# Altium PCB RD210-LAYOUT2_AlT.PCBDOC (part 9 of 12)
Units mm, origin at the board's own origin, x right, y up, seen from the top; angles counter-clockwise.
Board outline 250 x 123 mm, 4 copper layers (TOP, Mid-Layer 1, Mid-Layer 2, BOTTOM), stack 0.711 mm thick; 1043 components, 659 nets, 2786 pads, 1228 vias.
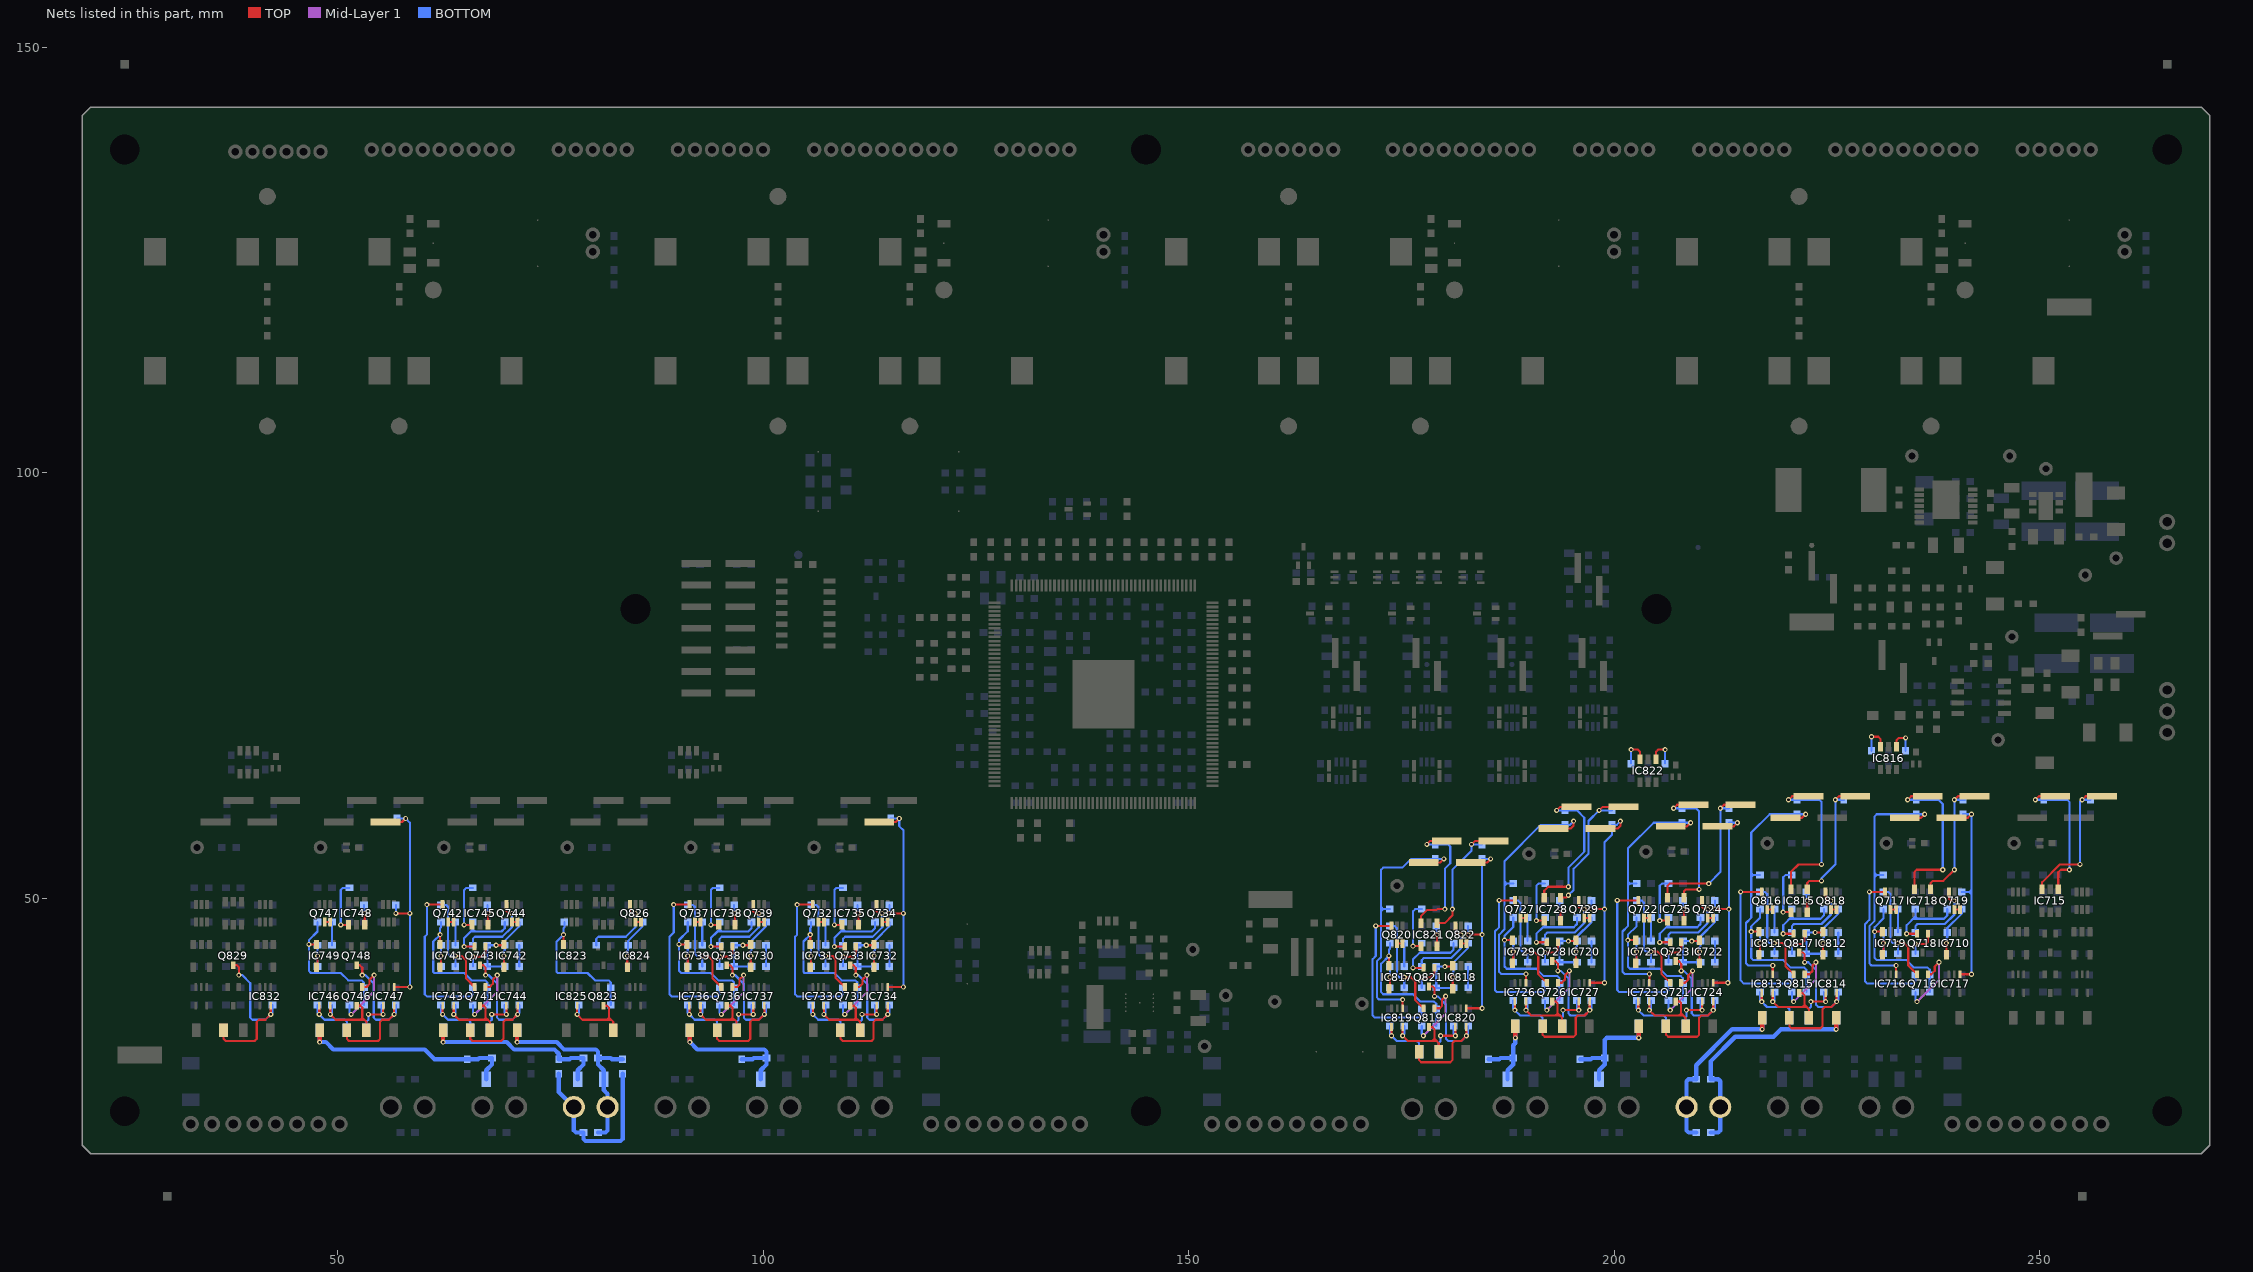
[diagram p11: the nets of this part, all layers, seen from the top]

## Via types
v1: diameter 0.6, hole 0.3, TOP to BOTTOM, 1134 vias
v2: diameter 1, hole 0.5, TOP to BOTTOM, 94 vias

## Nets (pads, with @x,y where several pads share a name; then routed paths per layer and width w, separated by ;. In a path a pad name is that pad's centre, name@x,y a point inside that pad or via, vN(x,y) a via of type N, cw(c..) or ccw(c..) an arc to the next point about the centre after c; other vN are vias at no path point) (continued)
N00300061: Q717.2 Q717.3 | length 0.6
  TOP w0.25: Q717.2@232.5,48.725 Q717.3@233.15,48.725
N00300062: C720.2 IC719.3 R822.1 R824.2 | length 16.8
  TOP w0.25: v1(230.625,46.1) IC719.3@231.55,46.1
  BOTTOM w0.25: C720.2@231.65,48.75 231.65,47.65 230.625,46.625 v1(230.625,46.1) 230.625,43 230.875,42.75 234.375,42.75 235.25,41.875 236.85,41.875 237.1,41.625 R822.1@237.1,41 R824.2@237.1,39
N00300063: Q717.6 R822.2 | length 19.4
  TOP w0.25: v1(230,50.775) Q717.6@231.85,50.775
  BOTTOM w0.25: v1(230,50.775) 230,47.5 229.5,47 229.5,40.25 229.75,40 235.15,40 235.4,40.25 R822.2@235.4,41
N00300064: Q716.1 R824.1 | length 9.1
  TOP w0.25: Q716.1@236.9,41.1 237.282,41.1 237.678,41.496 237.678,42.004 v1(238.186,42.512)
  Mid-Layer 1 w0.25: v1(235.6,37.875) 238.186,40.461 v1(238.186,42.512)
  BOTTOM w0.25: R824.1@235.4,39 235.4,38.075 v1(235.6,37.875)
N00300065: Q716.2 R826.1 R828.2 | length 13.7
  TOP w0.25: v1(233.35,44.75) 234.109,44.75 234.569,44.29 234.569,42.131 Q716.2@235.6,41.1
  BOTTOM w0.25: R828.2@231.65,50.75 232.25,50.75 232.5,50.5 232.5,45 232.75,44.75 v1(233.35,44.75) R826.1@233.35,43.5
N00300066: IC719.4 R820.1 R826.2 | length 3.9
  TOP w0.25: IC719.4@231.55,43.4 231.65,43.5 v1(231.65,44.75)
  BOTTOM w0.25: R826.2@231.65,43.5 v1(231.65,44.75) R820.1@231.65,46
N00300069: C720.1 R820.2 | length 2.8
  BOTTOM w0.25: R820.2@233.35,46 C720.1@233.35,48.75
N00300070: Q719.2 Q719.3 | length 0.7
  TOP w0.25: Q719.2@240,48.725 Q719.3@240.65,48.725
N00300071: Q719.6 R823.2 | length 9.1
  TOP w0.25: Q719.6@239.35,50.775 239.35,50 239.6,49.75 v1(240,49.75)
  BOTTOM w0.25: R823.2@235.4,46 235.4,46.75 235.65,47 238.875,47 240,48.125 v1(240,49.75)
N00300073: Q718.1 R825.1 | length 3.7
  TOP w0.25: v1(235.4,44.671) 236.662,44.671 236.9,44.909 Q718.1@236.9,45.85
  BOTTOM w0.25: R825.1@235.4,43.5 v1(235.4,44.671)
N00300074: Q718.2 R827.1 R829.2 | length 9.8
  TOP w0.25: v1(234.375,45.85) Q718.2@235.6,45.85
  BOTTOM w0.25: v1(234.375,45.85) 234.375,46.85 235.4,47.875 ; 235.15,47.625 235.65,47.625 ; R829.2@235.4,48.75 235.4,47.875 ; R827.1@239.15,48.75 239.15,48 238.775,47.625 235.65,47.625 ; 235.4,47.875 235.65,47.625
N00300075: IC710.4 R821.1 R827.2 | length 6.1
  TOP w0.25: IC710.4@239.05,43.4 v1(239.05,44.75)
  BOTTOM w0.25: v1(239.05,44.75) 239.05,45.3 239.15,45.4 R821.1@239.15,46 239.15,46.525 240.85,48.225 R827.2@240.85,48.75
N00300077: IC721.4 R740.1 R746.2 | length 3.9
  TOP w0.25: IC721.4@202.55,42.4 202.65,42.5 v1(202.65,43.75)
  BOTTOM w0.25: R746.2@202.65,42.5 v1(202.65,43.75) R740.1@202.65,45
N00300078: C730.1 R740.2 | length 2.7
  BOTTOM w0.25: R740.2@204.35,45 C730.1@204.35,47.75
N00300081: IC720.4 R841.1 R847.2 | length 6.1
  TOP w0.25: IC720.4@195.55,42.4 v1(195.55,43.75)
  BOTTOM w0.25: v1(195.55,43.75) 195.55,44.3 195.65,44.4 R841.1@195.65,45 195.65,45.525 197.35,47.225 R847.2@197.35,47.75
N00300082: C730.2 IC721.3 R742.1 R744.2 | length 16.8
  TOP w0.25: v1(201.625,45.1) IC721.3@202.55,45.1
  BOTTOM w0.25: C730.2@202.65,47.75 202.65,46.75 201.625,45.725 v1(201.625,45.1) 201.625,42 201.875,41.75 205.375,41.75 206.25,40.875 207.85,40.875 208.1,40.625 R742.1@208.1,40 R744.2@208.1,38
N00300083: Q723.1 R745.1 | length 3.7
  TOP w0.25: v1(206.4,43.655) 207.579,43.655 207.9,43.976 Q723.1@207.9,44.85
  BOTTOM w0.25: R745.1@206.4,42.5 v1(206.4,43.655)
N00300085: Q723.2 R747.1 R749.2 | length 9.8
  TOP w0.25: v1(205.375,44.85) Q723.2@206.6,44.85
  BOTTOM w0.25: v1(205.375,44.85) 205.375,45.85 206.15,46.625 ; R749.2@206.4,47.75 206.4,46.875 ; R747.1@210.15,47.75 210.15,47 209.775,46.625 206.65,46.625 ; 206.15,46.625 206.4,46.875 ; 206.15,46.625 206.65,46.625 ; 206.4,46.875 206.65,46.625
N00300087: Q728.2 R847.1 R849.2 | length 9.8
  TOP w0.25: v1(190.875,44.85) Q728.2@192.1,44.85
  BOTTOM w0.25: v1(190.875,44.85) 190.875,45.85 191.65,46.625 ; R849.2@191.9,47.75 191.9,46.875 ; R847.1@195.65,47.75 195.65,47 195.275,46.625 192.15,46.625 ; 191.65,46.625 191.9,46.875 ; 191.65,46.625 192.15,46.625 ; 191.9,46.875 192.15,46.625
N00300088: Q729.6 R843.2 | length 9.1
  TOP w0.25: Q729.6@195.85,49.775 195.85,49 196.1,48.75 v1(196.5,48.75)
  BOTTOM w0.25: R843.2@191.9,45 191.9,45.75 192.15,46 195.375,46 196.5,47.125 v1(196.5,48.75)
N00300090: C741.2 IC720.3 R843.1 R845.2 | length 6.5
  TOP w0.25: v1(194.625,45) 195.45,45 IC720.3@195.55,45.1
  BOTTOM w0.25: v1(194.625,45) R843.1@193.6,45 R845.2@193.6,42.5 C741.2@195.65,42.5
N00300093: C742.2 C743.2 R851.1 R853.2 R858.2 | length 11
  TOP w0.5: v1(188.4,33.625) R853.2@188.4,35
  BOTTOM w0.5: R858.2@185.25,31.1 186.5,31.1 186.65,31.25 C743.2@188.15,31.25 ; C742.2@187.475,28.75 187.475,29.825 188.15,30.5 C743.2@188.15,31.25 ; R851.1@188.4,35 v1(188.4,33.625) 188.4,33 188.15,32.75 C743.2@188.15,31.25
N00300094: C740.2 IC729.3 R842.1 R844.2 | length 16.8
  TOP w0.25: v1(187.125,45.1) IC729.3@188.05,45.1
  BOTTOM w0.25: C740.2@188.15,47.75 188.15,46.65 187.125,45.625 v1(187.125,45.1) 187.125,42 187.375,41.75 190.875,41.75 191.75,40.875 193.35,40.875 193.6,40.625 R842.1@193.6,40 R844.2@193.6,38
N00300095: Q729.2 Q729.3 | length 0.6
  TOP w0.25: Q729.2@196.5,47.725 Q729.3@197.15,47.725
N00300096: C740.1 R840.2 | length 2.7
  BOTTOM w0.25: R840.2@189.85,45 C740.1@189.85,47.75
N00300097: IC729.4 R840.1 R846.2 | length 3.9
  TOP w0.25: IC729.4@188.05,42.4 188.15,42.5 v1(188.15,43.75)
  BOTTOM w0.25: R846.2@188.15,42.5 v1(188.15,43.75) R840.1@188.15,45
N00300098: Q726.2 R846.1 R848.2 | length 13.7
  TOP w0.25: v1(189.85,43.75) 190.609,43.75 191.085,43.274 191.085,41.115 Q726.2@192.1,40.1
  BOTTOM w0.25: R848.2@188.15,49.75 188.75,49.75 189,49.5 189,44 189.25,43.75 v1(189.85,43.75) R846.1@189.85,42.5
N00300099: C734.2 IC723.4 R751.2 | length 6.8
  TOP w0.25: v1(202.85,36.875) IC723.4@202.85,37.9
  BOTTOM w0.25: C734.2@202.65,38 202.65,37.075 v1(202.85,36.875) 203.475,36.25 205.85,36.25 206.1,36 R751.2@206.1,35
N00300100: C735.1 IC724.5 Q723.3 R753.1 | length 21.5
  TOP w0.25: R753.1@206.1,35 206.1,34 206.35,33.75 209.75,33.75 210,34 210,36 210.25,36.25 211.025,36.25 v1(211.65,36.875) IC724.5@211.65,37.9 ; Q723.3@207.25,42.65 207.568,42.65 207.9,42.318 v1(207.9,41.5)
  BOTTOM w0.25: v1(207.9,41.5) 208.21,41.5 209.125,40.585 209.125,36.5 209.375,36.25 211.025,36.25 v1(211.65,36.875) 211.85,37.075 C735.1@211.85,38
N00300103: C745.1 IC727.5 Q728.3 R853.1 | length 21.6
  TOP w0.25: R853.1@191.6,35 191.6,34 191.85,33.75 195.25,33.75 195.5,34 195.5,36 195.75,36.25 196.525,36.25 v1(197.15,36.875) IC727.5@197.15,37.9 ; Q728.3@192.75,42.65 193.101,42.65 193.4,42.351 v1(193.4,41.5)
  BOTTOM w0.25: v1(193.4,41.5) 193.732,41.5 194.625,40.607 194.625,36.5 194.875,36.25 196.525,36.25 v1(197.15,36.875) 197.35,37.075 C745.1@197.35,38
N00300105: Q722.6 R742.2 | length 20
  TOP w0.25: v1(200.375,49.775) Q722.6@202.85,49.775
  BOTTOM w0.25: v1(200.375,49.775) 200.375,39.25 200.625,39 206.15,39 206.4,39.25 R742.2@206.4,40
N00300107: C731.1 R741.2 | length 2.5
  BOTTOM w0.25: C731.1@211.85,42.5 R741.2@211.85,45
N00300108: Q721.2 R746.1 R748.2 | length 13.7
  TOP w0.25: v1(204.35,43.75) 205.109,43.75 205.585,43.274 205.585,41.115 Q721.2@206.6,40.1
  BOTTOM w0.25: R748.2@202.65,49.75 203.25,49.75 203.5,49.5 203.5,44 203.75,43.75 v1(204.35,43.75) R746.1@204.35,42.5
N00300111: C744.2 IC726.4 R851.2 | length 6.8
  TOP w0.25: v1(188.35,36.875) IC726.4@188.35,37.9
  BOTTOM w0.25: C744.2@188.15,38 188.15,37.075 v1(188.35,36.875) 188.975,36.25 191.35,36.25 191.6,36 R851.2@191.6,35
N00300112: Q727.6 R842.2 | length 19.4
  TOP w0.25: v1(186.5,49.775) Q727.6@188.35,49.775
  BOTTOM w0.25: v1(186.5,49.775) 186.5,46.625 186,46.125 186,39.25 186.25,39 191.65,39 191.9,39.25 R842.2@191.9,40
N00300113: C744.1 IC726.5 Q726.3 R850.2 | length 10.5
  TOP w0.25: IC726.5@189.65,37.9 v1(189.65,36.875) 190.275,36.25 193.125,36.25 ; Q726.3@192.75,37.9 193.141,37.9 193.375,37.666 193.375,36.525 ; R850.2@193.9,35 193.9,36 193.65,36.25 ; 193.125,36.25 193.375,36.5 193.375,36.525 ; 193.125,36.25 193.65,36.25 ; 193.375,36.525 193.65,36.25
  BOTTOM w0.25: v1(189.65,36.875) 189.85,37.075 C744.1@189.85,38
N00300115: C735.2 IC724.4 R752.2 | length 6
  TOP w0.25: v1(208.5,36.875) v1(210.35,36.875) IC724.4@210.35,37.9
  BOTTOM w0.25: R752.2@208.4,35 208.4,36.025 208.5,36.125 v1(208.5,36.875) ; C735.2@210.15,38 210.15,37.075 v1(210.35,36.875)
N00300117: Q728.1 R845.1 | length 3.7
  TOP w0.25: v1(191.9,43.655) 193.101,43.655 193.4,43.954 Q728.1@193.4,44.85
  BOTTOM w0.25: R845.1@191.9,42.5 v1(191.9,43.655)
N00300122: C731.2 IC722.3 R743.1 R745.2 | length 6.5
  TOP w0.25: v1(209.125,45) 209.95,45 IC722.3@210.05,45.1
  BOTTOM w0.25: v1(209.125,45) R743.1@208.1,45 R745.2@208.1,42.5 C731.2@210.15,42.5
N00300123: IC722.4 R741.1 R747.2 | length 6.1
  TOP w0.25: IC722.4@210.05,42.4 v1(210.05,43.75)
  BOTTOM w0.25: v1(210.05,43.75) 210.05,44.3 210.15,44.4 R741.1@210.15,45 210.15,45.525 211.85,47.225 R747.2@211.85,47.75
N00300124: C741.1 R841.2 | length 2.5
  BOTTOM w0.25: C741.1@197.35,42.5 R841.2@197.35,45
N00300126: Q727.2 Q727.3 | length 0.7
  TOP w0.25: Q727.2@189,47.725 Q727.3@189.65,47.725
N00300131: C734.1 IC723.5 Q721.3 R750.2 | length 10.5
  TOP w0.25: IC723.5@204.15,37.9 v1(204.15,36.875) 204.775,36.25 207.625,36.25 ; Q721.3@207.25,37.9 207.706,37.9 207.875,37.731 207.875,36.525 207.888,36.512 ; R750.2@208.4,35 208.4,36 208.15,36.25 ; 207.625,36.25 207.888,36.512 ; 207.625,36.25 208.15,36.25 ; 207.888,36.512 208.15,36.25
  BOTTOM w0.25: v1(204.15,36.875) 204.35,37.075 C734.1@204.35,38
N00300133: IC725.6 R756.1 | length 2.4
  TOP w0.25: IC725.6@208.2,47.4 v1(208.2,48.75)
  BOTTOM w0.25: R756.1@208.1,49.75 208.1,49.225 208.2,49.125 v1(208.2,48.75)
N00300134: C732.2 C733.2 R751.1 R753.2 R758.2 | length 14.7
  TOP w0.5: v1(202.9,33.625) R753.2@202.9,35
  BOTTOM w0.5: R758.2@196,31.1 197.25,31.1 197.4,31.25 C733.2@198.9,31.25 ; C732.2@198.225,28.75 198.225,29.825 198.9,30.5 C733.2@198.9,31.25 ; R751.1@202.9,35 v1(202.9,33.625) 199.15,33.625 198.9,33.375 C733.2@198.9,31.25
N00300135: IC725.4 R757.1 | length 6.2
  TOP w0.25: v1(205.375,47.4) IC725.4@206.3,47.4
  BOTTOM w0.25: v1(205.375,47.4) 205.375,51.5 205.625,51.75 R757.1@206.4,51.75
N00300136: Q722.2 Q722.3 | length 0.7
  TOP w0.25: Q722.2@203.5,47.725 Q722.3@204.15,47.725
N00300138: Q721.1 R744.1 | length 9.1
  TOP w0.25: Q721.1@207.9,40.1 208.342,40.1 208.722,40.48 208.722,40.988 v1(209.23,41.496)
  Mid-Layer 1 w0.25: v1(206.6,36.875) 209.23,39.505 v1(209.23,41.496)
  BOTTOM w0.25: R744.1@206.4,38 206.4,37.075 v1(206.6,36.875)
N00300139: Q724.2 Q724.3 | length 0.7
  TOP w0.25: Q724.2@211,47.725 Q724.3@211.65,47.725
N00300141: Q724.6 R743.2 | length 9.1
  TOP w0.25: Q724.6@210.35,49.775 210.35,49 210.6,48.75 v1(211,48.75)
  BOTTOM w0.25: R743.2@206.4,45 206.4,45.75 206.65,46 209.875,46 211,47.125 v1(211,48.75)
N00300142: C745.2 IC727.4 R852.2 | length 6
  TOP w0.25: v1(194,36.875) v1(195.85,36.875) IC727.4@195.85,37.9
  BOTTOM w0.25: R852.2@193.9,35 193.9,36.025 194,36.125 v1(194,36.875) ; C745.2@195.65,38 195.65,37.075 v1(195.85,36.875)
N00300148: IC728.6 R856.1 | length 2.4
  TOP w0.25: IC728.6@193.7,47.4 v1(193.7,48.75)
  BOTTOM w0.25: R856.1@193.6,49.75 193.6,49.225 193.7,49.125 v1(193.7,48.75)
N00300149: IC728.4 R857.1 | length 6.2
  TOP w0.25: v1(190.875,47.4) IC728.4@191.8,47.4
  BOTTOM w0.25: v1(190.875,47.4) 190.875,51.5 191.125,51.75 R857.1@191.9,51.75
N00300150: Q726.1 R844.1 | length 9.2
  TOP w0.25: Q726.1@193.4,40.1 193.863,40.1 194.244,40.481 194.244,40.988 v1(194.752,41.496)
  Mid-Layer 1 w0.25: v1(192.1,36.875) 194.752,39.527 v1(194.752,41.496)
  BOTTOM w0.25: R844.1@191.9,38 191.9,37.075 v1(192.1,36.875)
N00300153: CN501.2 IC715.1 R701.2 | length 18
  TOP w0.25: v1(249.5,61.6) 249.92,62.02 CN501.2@251.85,62.02 ; IC715.1@252.2,51.1 252.2,53.075 252.5,53.375 v1(253.5,53.375)
  BOTTOM w0.25: v1(249.5,61.6) R701.2@250.5,61.6 253.25,61.6 253.5,61.35 v1(253.5,53.375)
N00300157: IC816.6 R706.1 | length 3.7
  TOP w0.25: v1(230.25,69) 231.05,69 231.3,68.75 IC816.6@231.3,67.85
  BOTTOM w0.25: R706.1@230.25,67.35 v1(230.25,69)
N00300158: IC816.4 R906.1 | length 3.5
  TOP w0.25: IC816.4@233.2,67.85 233.2,68.625 233.45,68.875 v1(234.25,68.875)
  BOTTOM w0.25: R906.1@234.25,67.35 v1(234.25,68.875)
N00300160: CN503.2 IC715.3 R901.2 | length 17.4
  TOP w0.25: IC715.3@250.3,51.1 250.3,51.925 252.375,54 v1(254.75,54) ; v1(255,61.6) 255.42,62.02 CN503.2@257.35,62.02
  BOTTOM w0.25: v1(254.75,54) 254.75,61.35 v1(255,61.6) R901.2@256,61.6
N00300161: CN921.1 IC819.1 R717.1 R954.1 | length 31.3
  TOP w0.25: IC819.1@175.15,37.1 v1(175.15,38.125) ; CN921.1@177.65,54.23 179.58,54.23 v1(180,54.65)
  BOTTOM w0.25: R954.1@173.65,48.75 172.875,48.75 ; v1(175.15,38.125) 172.375,38.125 172.125,38.375 172.125,42.625 172.625,43.125 172.625,48.5 ; v1(180,54.65) R717.1@179,54.65 176.15,54.65 175.125,53.625 172.875,53.625 172.625,53.375 172.625,49 ; 172.625,48.5 172.625,49 ; 172.625,48.5 172.875,48.75 ; 172.625,49 172.875,48.75
N00300164: CN913.2 IC815.1 R916.2 | length 16.2
  TOP w0.25: IC815.1@222.7,51.1 222.7,51.825 222.95,52.075 v1(224.375,52.075) ; v1(226,61.6) 226.42,62.02 CN913.2@228.35,62.02
  BOTTOM w0.25: v1(224.375,52.075) 224.375,52.375 226,54 v1(226,61.6) R916.2@227,61.6
N00300165: CN911.1 IC813.1 R716.1 R934.1 | length 31.2
  TOP w0.25: IC813.1@218.65,41.1 v1(218.65,42.125) ; CN911.1@220.15,59.48 222.08,59.48 v1(222.5,59.9)
  BOTTOM w0.25: R934.1@217.15,52.75 216.375,52.75 ; v1(218.65,42.125) 215.75,42.125 215.5,42.375 215.5,47.125 216.125,47.75 216.125,52.5 ; v1(222.5,59.9) R716.1@221.5,59.9 218.275,59.9 216.125,57.75 216.125,53 ; 216.125,52.5 216.375,52.75 ; 216.125,52.5 216.125,53 ; 216.125,53 216.375,52.75
N00300168: C924.1 IC819.5 Q819.3 R950.2 | length 10.4
  TOP w0.25: IC819.5@175.15,34.9 v1(175.15,33.875) 175.775,33.25 178.65,33.25 ; Q819.3@178.25,34.9 178.638,34.9 178.9,34.638 178.9,33.5 ; R950.2@179.4,32 179.4,33 179.15,33.25 ; 178.65,33.25 179.15,33.25 ; 178.65,33.25 178.9,33.5 ; 178.9,33.5 179.15,33.25
  BOTTOM w0.25: v1(175.15,33.875) 175.35,34.075 C924.1@175.35,35
N00300169: CN923.1 IC820.1 R917.1 R955.1 | length 25.6
  TOP w0.25: IC820.1@182.65,37.1 v1(184.5,37.1) ; v1(182.85,45.75) v1(184.5,45.75) ; CN923.1@183.15,54.23 185.08,54.23 v1(185.5,54.65)
  BOTTOM w0.25: v1(182.85,45.75) R955.1@182.85,46.75 ; v1(184.5,37.1) v1(184.5,45.75) R917.1@184.5,54.65 v1(185.5,54.65)
N00300170: CN923.2 IC821.1 R917.2 | length 15.5
  TOP w0.25: IC821.1@179.2,47.1 180.1,47.1 181,48 v1(181,48.75) ; v1(183.25,56.35) 183.67,56.77 CN923.2@185.85,56.77
  BOTTOM w0.25: v1(181,48.75) 181,53.375 183.25,55.625 v1(183.25,56.35) R917.2@184.5,56.35
N00300171: CN504.1 IC716.1 R711.1 R834.1 | length 31.8
  TOP w0.25: IC716.1@233.15,41.1 v1(233.15,42.125) ; CN504.1@234.15,59.48 236.08,59.48 v1(236.5,59.9)
  BOTTOM w0.25: R834.1@231.65,52.75 230.875,52.75 ; v1(233.15,42.125) 230.25,42.125 230,42.375 230,46.75 230.625,47.375 230.625,52.5 ; v1(236.5,59.9) R711.1@235.5,59.9 230.875,59.9 230.625,59.65 230.625,53 ; 230.625,52.5 230.875,52.75 ; 230.625,52.5 230.625,53 ; 230.625,53 230.875,52.75
N00300173: CN506.1 IC717.1 R835.1 R911.1 | length 25.3
  TOP w0.25: CN506.1@239.65,59.48 241.58,59.48 v1(242,59.9) ; IC717.1@240.65,41.1 v1(242,41.1)
  BOTTOM w0.25: R835.1@240.85,50.75 241.75,50.75 ; R911.1@241,59.9 v1(242,59.9) 242,51 ; v1(242,41.1) 242,50.5 ; 241.75,50.75 242,51 ; 241.75,50.75 242,50.5 ; 242,50.5 242,51
N00300179: C924.2 IC819.4 R951.2 | length 6.8
  TOP w0.25: v1(173.85,33.875) IC819.4@173.85,34.9
  BOTTOM w0.25: C924.2@173.65,35 173.65,34.075 v1(173.85,33.875) 174.475,33.25 176.85,33.25 177.1,33 R951.2@177.1,32
N00300180: C925.2 IC820.4 R952.2 | length 5.9
  TOP w0.25: v1(179.625,33.875) v1(181.35,33.875) IC820.4@181.35,34.9
  BOTTOM w0.25: R952.2@179.4,32 179.4,33.025 179.625,33.25 v1(179.625,33.875) ; C925.2@181.15,35 181.15,34.075 v1(181.35,33.875)
N00300183: C925.1 IC820.5 Q821.3 R953.1 | length 21.6
  TOP w0.25: R953.1@177.1,32 177.1,31 177.35,30.75 180.75,30.75 181,31 181,33 181.25,33.25 182.025,33.25 v1(182.65,33.875) IC820.5@182.65,34.9 ; Q821.3@178.25,39.65 178.714,39.65 178.9,39.464 v1(178.9,38.5)
  BOTTOM w0.25: v1(178.9,38.5) 179.27,38.5 180.25,37.519 180.25,33.5 180.5,33.25 182.025,33.25 v1(182.65,33.875) 182.85,34.075 C925.1@182.85,35
N00300185: IC821.4 R957.1 | length 6.2
  TOP w0.25: v1(176.375,44.4) IC821.4@177.3,44.4
  BOTTOM w0.25: v1(176.375,44.4) 176.375,48.5 176.625,48.75 R957.1@177.4,48.75
N00300186: IC821.6 R956.1 | length 2.4
  TOP w0.25: IC821.6@179.2,44.4 v1(179.2,45.75)
  BOTTOM w0.25: R956.1@179.1,46.75 179.1,46.225 179.2,46.125 v1(179.2,45.75)
N00300187: Q820.6 R942.2 | length 19.3
  TOP w0.25: v1(172,46.775) Q820.6@173.85,46.775
  BOTTOM w0.25: v1(172,46.775) 172,43.25 171.625,42.875 171.625,36.25 171.875,36 177.15,36 177.4,36.25 R942.2@177.4,37
N00300188: Q820.2 Q820.3 | length 0.7
  TOP w0.25: Q820.2@174.5,44.725 Q820.3@175.15,44.725
N00300189: Q819.1 R944.1 | length 9.2
  TOP w0.25: Q819.1@178.9,37.1 179.512,37.1 179.766,37.354 179.766,38.067 v1(180.211,38.511)
  Mid-Layer 1 w0.25: v1(177.6,33.875) 180.211,36.486 v1(180.211,38.511)
  BOTTOM w0.25: R944.1@177.4,35 177.4,34.075 v1(177.6,33.875)
N00300190: Q819.2 R946.1 R948.2 | length 13.7
  TOP w0.25: v1(175.35,40.75) 176.116,40.75 176.64,40.226 176.64,38.06 Q819.2@177.6,37.1
  BOTTOM w0.25: R948.2@173.65,46.75 174.25,46.75 174.5,46.5 174.5,41 174.75,40.75 v1(175.35,40.75) R946.1@175.35,39.5
N00300191: CN911.2 IC815.3 R716.2 | length 19.8
  TOP w0.25: v1(220.5,61.6) 220.92,62.02 CN911.2@222.85,62.02 ; IC815.3@220.8,51.1 220.8,53.125 221.675,54 v1(224.375,54)
  BOTTOM w0.25: v1(220.5,61.6) R716.2@221.5,61.6 224.125,61.6 224.375,61.35 v1(224.375,54)
N00300193: C920.2 IC817.3 R942.1 R944.2 | length 17
  TOP w0.25: IC817.3@173.55,42.1 v1(173.55,43.25)
  BOTTOM w0.25: C920.2@173.65,44.75 173.65,44.1 173.55,44 v1(173.55,43.25) 172.625,42.325 172.625,39 172.875,38.75 176.375,38.75 177.25,37.875 178.85,37.875 179.1,37.625 R942.1@179.1,37 R944.2@179.1,35
N00300194: IC817.4 R940.1 R946.2 | length 3.9
  TOP w0.25: IC817.4@173.55,39.4 173.65,39.5 v1(173.65,40.75)
  BOTTOM w0.25: R946.2@173.65,39.5 v1(173.65,40.75) R940.1@173.65,42
N00300195: C920.1 R940.2 | length 2.7
  BOTTOM w0.25: R940.2@175.35,42 C920.1@175.35,44.75
N00300198: Q822.2 Q822.3 | length 0.6
  TOP w0.25: Q822.2@182,44.725 Q822.3@182.65,44.725
N00300199: C921.2 IC818.3 R943.1 R945.2 | length 6.5
  TOP w0.25: v1(180.125,42) 180.95,42 IC818.3@181.05,42.1
  BOTTOM w0.25: v1(180.125,42) R943.1@179.1,42 R945.2@179.1,39.5 C921.2@181.15,39.5
N00300200: Q822.6 R943.2 | length 9.1
  TOP w0.25: Q822.6@181.35,46.775 181.35,46 181.6,45.75 v1(182,45.75)
  BOTTOM w0.25: R943.2@177.4,42 177.4,42.75 177.65,43 180.875,43 182,44.125 v1(182,45.75)
N00300201: Q821.1 R945.1 | length 3.6
  TOP w0.25: v1(177.4,40.734) 178.496,40.734 178.9,41.138 Q821.1@178.9,41.85
  BOTTOM w0.25: R945.1@177.4,39.5 v1(177.4,40.734)
N00300202: Q821.2 R947.1 R949.2 | length 9.8
  TOP w0.25: v1(176.375,41.85) Q821.2@177.6,41.85
  BOTTOM w0.25: v1(176.375,41.85) 176.375,42.85 177.15,43.625 ; R949.2@177.4,44.75 177.4,43.875 ; R947.1@181.15,44.75 181.15,44 180.775,43.625 177.65,43.625 ; 177.15,43.625 177.4,43.875 ; 177.15,43.625 177.65,43.625 ; 177.4,43.875 177.65,43.625
N00300203: IC818.4 R941.1 R947.2 | length 6.1
  TOP w0.25: IC818.4@181.05,39.4 v1(181.05,40.75)
  BOTTOM w0.25: v1(181.05,40.75) 181.05,41.3 181.15,41.4 R941.1@181.15,42 181.15,42.525 182.85,44.225 R947.2@182.85,44.75
N00300207: C921.1 R941.2 | length 2.5
  BOTTOM w0.25: C921.1@182.85,39.5 R941.2@182.85,42
N00300210: IC822.6 R707.1 | length 3.7
  TOP w0.25: v1(202,67.5) 202.8,67.5 203.05,67.25 IC822.6@203.05,66.35
  BOTTOM w0.25: R707.1@202,65.85 v1(202,67.5)
N00300213: IC822.4 R907.1 | length 3.7
  TOP w0.25: IC822.4@204.95,66.35 204.95,67.25 205.2,67.5 v1(206,67.5)
  BOTTOM w0.25: R907.1@206,65.85 v1(206,67.5)
N00300216: CN513.2 IC725.3 R902.2 | length 19.3
  TOP w0.25: IC725.3@206.3,50.1 206.3,51.5 206.55,51.75 v1(211.125,51.75) ; v1(212.5,60.6) 212.92,61.02 CN513.2@214.85,61.02
  BOTTOM w0.25: v1(211.125,51.75) 212.5,53.125 v1(212.5,60.6) R902.2@213.5,60.6
N00300217: CN516.2 IC728.1 R912.2 | length 17
  TOP w0.25: IC728.1@193.7,50.1 194.35,50.1 v1(194.625,50.375) ; v1(198.25,60.35) 198.67,60.77 CN516.2@201.1,60.77
  BOTTOM w0.25: v1(194.625,50.375) 195.25,51 195.25,53.5 197,55.25 197,59.1 v1(198.25,60.35) R912.2@199.75,60.35
N00300218: CN506.2 IC718.1 R911.2 | length 16.4
  TOP w0.25: IC718.1@237.2,51.1 237.2,51.825 237.45,52.075 238.7,52.075 v1(240,53.375) ; v1(240,61.6) 240.42,62.02 CN506.2@242.35,62.02 CN506.2@242.6,62.02
  BOTTOM w0.25: v1(240,53.375) v1(240,61.6) R911.2@241,61.6 R911.2@241.25,61.6
N00300219: CN513.1 IC724.1 R755.1 R902.1 | length 26.8
  TOP w0.25: IC724.1@211.65,40.1 v1(213.375,40.1) ; v1(211.85,48.75) v1(213.5,48.75) ; CN513.1@212.15,58.48 214.08,58.48 v1(214.5,58.9)
  BOTTOM w0.25: v1(211.85,48.75) R755.1@211.85,49.75 ; v1(213.375,40.1) 213.5,40.225 v1(213.5,48.75) R902.1@213.5,58.9 v1(214.5,58.9)
N00300220: CN514.2 IC728.3 R712.2 | length 18.9
  TOP w0.25: IC728.3@191.8,50.1 191.8,50.925 192.25,51.375 v1(194.625,51.375) ; v1(193.25,60.35) 193.67,60.77 CN514.2@195.6,60.77
  BOTTOM w0.25: v1(193.25,60.35) R712.2@194.25,60.35 195.65,60.35 196.5,59.5 196.5,55.5 194.625,53.625 v1(194.625,51.375)
N00300221: CN511.1 IC723.1 R702.1 R754.1 | length 31.7
  TOP w0.25: IC723.1@204.15,40.1 v1(204.15,41.125) ; CN511.1@206.65,58.48 208.58,58.48 v1(209,58.9)
  BOTTOM w0.25: R754.1@202.65,51.75 201.875,51.75 ; v1(204.15,41.125) 201.25,41.125 201,41.375 201,46.125 201.625,46.75 201.625,51.5 ; v1(209,58.9) R702.1@208,58.9 204.65,58.9 201.625,55.875 201.625,52 ; 201.625,51.5 201.875,51.75 ; 201.625,51.5 201.625,52 ; 201.625,52 201.875,51.75
N00300222: CN516.1 IC727.1 R855.1 R912.1 | length 27.4
  TOP w0.25: IC727.1@197.15,40.1 v1(198.875,40.1) ; v1(197.35,48.75) v1(198.875,48.75) ; CN516.1@198.4,58.23 200.437,58.23 200.75,58.543 v1(200.75,59.085)
  BOTTOM w0.25: v1(197.35,48.75) R855.1@197.35,49.75 ; v1(198.875,40.1) v1(198.875,48.75) 198.875,56.625 199.75,57.5 R912.1@199.75,58.65 200.314,58.65 v1(200.75,59.085)
N00300223: CN504.2 IC718.3 R711.2 | length 20.3
  TOP w0.25: v1(234.5,61.6) 234.92,62.02 CN504.2@236.85,62.02 CN504.2@237.1,62.02 ; IC718.3@235.3,51.1 235.3,53.125 235.55,53.375 v1(238.625,53.375)
  BOTTOM w0.25: v1(234.5,61.6) R711.2@235.5,61.6 238.125,61.6 238.625,61.1 v1(238.625,53.375)
N00300224: CN511.2 IC725.1 R702.2 | length 17.5
  TOP w0.25: v1(207,60.6) 207.42,61.02 CN511.2@209.35,61.02 ; IC725.1@208.2,50.1 208.2,50.825 208.45,51.075 v1(210,51.075)
  BOTTOM w0.25: v1(207,60.6) R702.2@208,60.6 209.625,60.6 210,60.225 v1(210,51.075)
N00300225: CN921.2 IC821.3 R717.2 | length 17
  TOP w0.25: IC821.3@177.3,47.1 177.3,47.925 178,48.625 179.125,48.625 179.25,48.75 v1(180.125,48.75) ; v1(178,56.35) 178.42,56.77 CN921.2@180.35,56.77
  BOTTOM w0.25: v1(178,56.35) R717.2@179,56.35 180.5,56.35 180.75,56.1 180.75,54.125 180.125,53.5 v1(180.125,48.75)
N00300228: CN514.1 IC726.1 R712.1 R854.1 | length 32.1
  TOP w0.25: IC726.1@189.65,40.1 v1(189.65,41.125) ; CN514.1@192.9,58.23 194.913,58.23 195.25,58.567 v1(195.25,59.085)
  BOTTOM w0.25: R854.1@188.15,51.75 187.375,51.75 ; v1(189.65,41.125) 186.75,41.125 186.5,41.375 186.5,45.75 187.125,46.375 187.125,51.5 ; v1(195.25,59.085) 194.805,58.641 194.241,58.641 R712.1@194.25,58.65 191.4,58.65 187.125,54.375 187.125,52 ; 187.125,51.5 187.375,51.75 ; 187.125,51.5 187.125,52 ; 187.125,52 187.375,51.75
N00300229: IC811.4 R920.1 R926.2 | length 3.9
  TOP w0.25: IC811.4@217.05,43.4 217.15,43.5 v1(217.15,44.75)
  BOTTOM w0.25: R926.2@217.15,43.5 v1(217.15,44.75) R920.1@217.15,46
N00300230: C910.1 R920.2 | length 2.8
  BOTTOM w0.25: R920.2@218.85,46 C910.1@218.85,48.75
N00300234: C910.2 IC811.3 R922.1 R924.2 | length 16.8
  TOP w0.25: v1(216.125,46.1) IC811.3@217.05,46.1
  BOTTOM w0.25: C910.2@217.15,48.75 217.15,47.75 216.125,46.725 v1(216.125,46.1) 216.125,43 216.375,42.75 219.875,42.75 220.75,41.875 222.35,41.875 222.6,41.625 R922.1@222.6,41 R924.2@222.6,39
N00300235: Q817.1 R925.1 | length 3.6
  TOP w0.25: v1(220.9,44.671) 222.057,44.671 222.4,45.014 Q817.1@222.4,45.85
  BOTTOM w0.25: R925.1@220.9,43.5 v1(220.9,44.671)
N00300237: Q817.2 R927.1 R929.2 | length 9.8
  TOP w0.25: v1(219.875,45.85) Q817.2@221.1,45.85
  BOTTOM w0.25: v1(219.875,45.85) 219.875,46.85 220.9,47.875 ; 220.65,47.625 221.15,47.625 ; R929.2@220.9,48.75 220.9,47.875 ; R927.1@224.65,48.75 224.65,48 224.275,47.625 221.15,47.625 ; 220.9,47.875 221.15,47.625
N00300251: C914.2 IC813.4 R931.2 | length 6.8
  TOP w0.25: v1(217.35,37.875) IC813.4@217.35,38.9
  BOTTOM w0.25: C914.2@217.15,39 217.15,38.075 v1(217.35,37.875) 217.975,37.25 220.35,37.25 220.6,37 R931.2@220.6,36
N00300252: C915.1 IC814.5 Q817.3 R933.1 | length 21.6
  TOP w0.25: R933.1@220.6,36 220.6,35 220.85,34.75 224.25,34.75 224.5,35 224.5,37 224.75,37.25 225.525,37.25 v1(226.15,37.875) IC814.5@226.15,38.9 ; Q817.3@221.75,43.65 222.184,43.65 222.4,43.434 v1(222.4,42.5)
  BOTTOM w0.25: v1(222.4,42.5) 222.831,42.5 223.75,41.581 223.75,37.5 224,37.25 225.525,37.25 v1(226.15,37.875) 226.35,38.075 C915.1@226.35,39
N00300253: C913.1 CN910.1 R930.1 R932.1 R939.2 | length 29.4
  TOP w0.5: v1(226.1,34.625) R930.1@226.1,36
  BOTTOM w0.5: C913.1@211.35,22.5 212.23,22.5 212.48,22.75 212.48,28.52 212.25,28.75 R939.2@211.35,28.75 211.35,30.85 214.25,33.75 218.75,33.75 219.625,34.625 v1(226.1,34.625) R932.1@226.1,36
N00300257: Q816.6 R922.2 | length 19.9
  TOP w0.25: v1(214.875,50.775) Q816.6@217.35,50.775
  BOTTOM w0.25: v1(214.875,50.775) 214.875,40.375 215.25,40 220.65,40 220.9,40.25 R922.2@220.9,41
N00300259: C911.1 R921.2 | length 2.5
  BOTTOM w0.25: C911.1@226.35,43.5 R921.2@226.35,46
N00300260: Q815.2 R926.1 R928.2 | length 13.8
  TOP w0.25: v1(218.85,44.75) 219.804,44.75 220.137,44.417 220.137,42.063 Q815.2@221.1,41.1
  BOTTOM w0.25: R928.2@217.15,50.75 217.75,50.75 218,50.5 218,45 218.25,44.75 v1(218.85,44.75) R926.1@218.85,43.5
N00300267: C915.2 IC814.4 R932.2 | length 5.9
  TOP w0.25: v1(223.125,37.875) v1(224.85,37.875) IC814.4@224.85,38.9
  BOTTOM w0.25: R932.2@222.9,36 222.9,37.025 223.125,37.25 v1(223.125,37.875) ; C915.2@224.65,39 224.65,38.075 v1(224.85,37.875)
N00300273: C913.2 CN910.2 R931.1 R933.2 R939.1 | length 22.1
  TOP w0.5: v1(217.4,34.625) R933.2@217.4,36
  BOTTOM w0.5: C913.2@209.65,22.5 208.77,22.5 208.52,22.75 208.52,28.52 208.75,28.75 R939.1@209.65,28.75 209.65,30.4 213.875,34.625 v1(217.4,34.625) R931.1@217.4,36
N00300274: C911.2 IC812.3 R923.1 R925.2 | length 6.5
  TOP w0.25: v1(223.625,46) 224.45,46 IC812.3@224.55,46.1
  BOTTOM w0.25: v1(223.625,46) R923.1@222.6,46 R925.2@222.6,43.5 C911.2@224.65,43.5
N00300275: IC812.4 R921.1 R927.2 | length 6.1
  TOP w0.25: IC812.4@224.55,43.4 v1(224.55,44.75)
  BOTTOM w0.25: v1(224.55,44.75) 224.55,45.3 224.65,45.4 R921.1@224.65,46 224.65,46.525 226.35,48.225 R927.2@226.35,48.75
N00300283: C914.1 IC813.5 Q815.3 R930.2 | length 10.4
  TOP w0.25: IC813.5@218.65,38.9 v1(218.65,37.875) 219.275,37.25 222.15,37.25 ; Q815.3@221.75,38.9 222.113,38.9 222.4,38.613 222.4,37.5 ; 222.65,37.25 222.15,37.25 ; R930.2@222.9,36 222.9,37 222.4,37.5 ; 222.15,37.25 222.4,37.5
  BOTTOM w0.25: v1(218.65,37.875) 218.85,38.075 C914.1@218.85,39
N00300285: IC815.6 R936.1 | length 2.4
  TOP w0.25: IC815.6@222.7,48.4 v1(222.7,49.75)
  BOTTOM w0.25: R936.1@222.6,50.75 222.6,50.225 222.7,50.125 v1(222.7,49.75)
N00300287: IC815.4 R937.1 | length 6.2
  TOP w0.25: v1(219.875,48.4) IC815.4@220.8,48.4
  BOTTOM w0.25: v1(219.875,48.4) 219.875,52.5 220.125,52.75 R937.1@220.9,52.75
N00300288: Q816.2 Q816.3 | length 0.6
  TOP w0.25: Q816.2@218,48.725 Q816.3@218.65,48.725
N00300290: Q815.1 R924.1 | length 9.2
  TOP w0.25: Q815.1@222.4,41.1 222.946,41.1 223.327,41.481 223.327,42.131 v1(223.708,42.512)
  Mid-Layer 1 w0.25: v1(221.1,37.875) 223.708,40.483 v1(223.708,42.512)
  BOTTOM w0.25: R924.1@220.9,39 220.9,38.075 v1(221.1,37.875)
N00300291: Q818.2 Q818.3 | length 0.7
  TOP w0.25: Q818.2@225.5,48.725 Q818.3@226.15,48.725
N00300293: Q818.6 R923.2 | length 9.1
  TOP w0.25: Q818.6@224.85,50.775 224.85,50 225.1,49.75 v1(225.5,49.75)
  BOTTOM w0.25: R923.2@220.9,46 220.9,46.75 221.15,47 224.375,47 225.5,48.125 v1(225.5,49.75)
N00400001: Q732.2 Q732.3 | length 0.6
  TOP w0.25: Q732.2@106.5,47.225 Q732.3@107.15,47.225
N00400002: C750.2 IC731.3 R762.1 R764.2 | length 16.9
  TOP w0.25: IC731.3@105.55,44.6 v1(105.55,45.75)
  BOTTOM w0.25: C750.2@105.65,47.25 105.65,46.6 105.55,46.5 v1(105.55,45.75) 104.75,44.95 104.75,41.375 104.875,41.25 108.375,41.25 109.25,40.375 110.85,40.375 111.1,40.125 R762.1@111.1,39.5 R764.2@111.1,37.5
N00400003: Q731.2 R766.1 R768.2 | length 13.7
  TOP w0.25: v1(107.35,43.25) 108.162,43.25 108.519,42.893 108.519,40.681 Q731.2@109.6,39.6
  BOTTOM w0.25: R768.2@105.65,49.25 106.25,49.25 106.5,49 106.5,43.5 106.75,43.25 v1(107.35,43.25) R766.1@107.35,42
N00400005: IC731.4 R760.1 R766.2 | length 3.9
  TOP w0.25: IC731.4@105.55,41.9 105.65,42 v1(105.65,43.25)
  BOTTOM w0.25: R766.2@105.65,42 v1(105.65,43.25) R760.1@105.65,44.5
N00400006: Q731.1 R764.1 | length 9.1
  TOP w0.25: Q731.1@110.9,39.6 111.322,39.6 111.685,39.963 111.685,40.471 v1(112.202,40.988)
  Mid-Layer 1 w0.25: v1(109.6,36.375) 112.202,38.977 v1(112.202,40.988)
  BOTTOM w0.25: R764.1@109.4,37.5 109.4,36.575 v1(109.6,36.375)
N00400007: Q732.6 R762.2 | length 19.1
  TOP w0.25: v1(104,49.275) Q732.6@105.85,49.275
  BOTTOM w0.25: v1(104,49.275) 104,45.75 103.75,45.5 103.75,38.75 104,38.5 109.15,38.5 109.4,38.75 R762.2@109.4,39.5
N00400008: C754.1 IC733.5 Q731.3 R770.2 | length 10.5
  TOP w0.25: IC733.5@107.15,37.4 v1(107.15,36.375) 107.775,35.75 110.65,35.75 ; Q731.3@110.25,37.4 110.678,37.4 110.9,37.178 110.9,36 ; R770.2@111.4,34.5 111.4,35.5 111.15,35.75 ; 110.65,35.75 111.15,35.75 ; 110.65,35.75 110.9,36 ; 110.9,36 111.15,35.75
  BOTTOM w0.25: v1(107.15,36.375) 107.35,36.575 C754.1@107.35,37.5
N00400010: C843.1 IC734.5 Q733.3 R773.1 | length 21.5
  TOP w0.25: R773.1@109.1,34.5 109.1,33.5 109.35,33.25 112.75,33.25 113,33.5 113,35.5 113.25,35.75 114.025,35.75 v1(114.65,36.375) IC734.5@114.65,37.4 ; Q733.3@110.25,42.15 110.627,42.15 110.9,41.877 v1(110.9,41)
  BOTTOM w0.25: v1(110.9,41) 111.174,41 112.25,39.924 112.25,36 112.5,35.75 114.025,35.75 v1(114.65,36.375) 114.85,36.575 C843.1@114.85,37.5
N00400011: CN926.1 IC734.1 R775.1 R903.1 | length 28
  TOP w0.25: CN926.1@113.65,58.98 115.58,58.98 v1(116,59.4) ; IC734.1@114.65,39.6 v1(116.5,39.6) ; v1(114.85,48.25) v1(116.5,48.25)
  BOTTOM w0.25: v1(114.85,48.25) R775.1@114.85,49.25 ; R903.1@115,59.4 v1(116,59.4) 116,58.5 116.5,58 v1(116.5,48.25) v1(116.5,39.6)
N00400012: C843.2 IC734.4 R772.2 | length 5.9
  TOP w0.25: v1(111.625,36.375) v1(113.35,36.375) IC734.4@113.35,37.4
  BOTTOM w0.25: R772.2@111.4,34.5 111.4,35.525 111.625,35.75 v1(111.625,36.375) ; C843.2@113.15,37.5 113.15,36.575 v1(113.35,36.375)
N00400013: Q733.2 R767.1 R769.2 | length 9.8
  TOP w0.25: v1(108.375,44.35) Q733.2@109.6,44.35
  BOTTOM w0.25: v1(108.375,44.35) 108.375,45.35 109.15,46.125 ; R769.2@109.4,47.25 109.4,46.375 ; R767.1@113.15,47.25 113.15,46.5 112.775,46.125 109.65,46.125 ; 109.15,46.125 109.4,46.375 ; 109.15,46.125 109.65,46.125 ; 109.4,46.375 109.65,46.125
N00400014: C751.1 R761.2 | length 2.5
  BOTTOM w0.25: C751.1@114.85,42 R761.2@114.85,44.5
N00400015: C762.2 C763.2 R871.1 R873.2 R878.2 | length 18.7
  TOP w0.5: v1(91.4,33.125) R873.2@91.4,34.5
  BOTTOM w0.5: R871.1@91.4,34.5 v1(91.4,33.125) 92.275,32.25 100.15,32.25 100.4,32 C763.2@100.4,31.25 ; R878.2@97.5,31.1 98.75,31.1 98.9,31.25 C763.2@100.4,31.25 ; C762.2@99.725,28.75 99.725,29.825 100.4,30.5 C763.2@100.4,31.25
N00400016: IC732.4 R761.1 R767.2 | length 6.1
  TOP w0.25: IC732.4@113.05,41.9 v1(113.05,43.25)
  BOTTOM w0.25: v1(113.05,43.25) 113.05,43.8 113.15,43.9 R761.1@113.15,44.5 113.15,45.025 114.85,46.725 R767.2@114.85,47.25
N00400019: C751.2 IC732.3 R763.1 R765.2 | length 6.5
  TOP w0.25: v1(112.125,44.5) 112.95,44.5 IC732.3@113.05,44.6
  BOTTOM w0.25: v1(112.125,44.5) R763.1@111.1,44.5 R765.2@111.1,42 C751.2@113.15,42
N00400020: Q733.1 R765.1 | length 3.6
  TOP w0.25: v1(109.4,43.147) 110.551,43.147 110.9,43.496 Q733.1@110.9,44.35
  BOTTOM w0.25: R765.1@109.4,42 v1(109.4,43.147)
N00400023: Q734.6 R763.2 | length 9.1
  TOP w0.25: Q734.6@113.35,49.275 113.35,48.5 113.6,48.25 v1(114,48.25)
  BOTTOM w0.25: R763.2@109.4,44.5 109.4,45.25 109.65,45.5 112.875,45.5 114,46.625 v1(114,48.25)
N00400025: Q734.2 Q734.3 | length 0.7
  TOP w0.25: Q734.2@114,47.225 Q734.3@114.65,47.225
N00400026: C754.2 IC733.4 R771.2 | length 6.8
  TOP w0.25: v1(105.85,36.375) IC733.4@105.85,37.4
  BOTTOM w0.25: C754.2@105.65,37.5 105.65,36.575 v1(105.85,36.375) 106.475,35.75 108.85,35.75 109.1,35.5 R771.2@109.1,34.5
N00400028: C750.1 R760.2 | length 2.7
  BOTTOM w0.25: R760.2@107.35,44.5 C750.1@107.35,47.25
N00400035: IC735.4 R777.1 | length 6.2
  TOP w0.25: v1(108.375,46.9) IC735.4@109.3,46.9
  BOTTOM w0.25: v1(108.375,46.9) 108.375,51 108.625,51.25 R777.1@109.4,51.25
N00400036: IC735.6 R776.1 | length 2.4
  TOP w0.25: IC735.6@111.2,46.9 v1(111.2,48.25)
  BOTTOM w0.25: R776.1@111.1,49.25 111.1,48.725 111.2,48.625 v1(111.2,48.25)
N00400039: IC745.6 R796.1 | length 2.4
  TOP w0.25: IC745.6@67.7,46.9 v1(67.7,48.25)
  BOTTOM w0.25: R796.1@67.6,49.25 67.6,48.725 67.7,48.625 v1(67.7,48.25)
N00400042: C869.2 IC743.4 R791.2 | length 6.8
  TOP w0.25: v1(62.35,36.375) IC743.4@62.35,37.4
  BOTTOM w0.25: C869.2@62.15,37.5 62.15,36.575 v1(62.35,36.375) 62.975,35.75 65.35,35.75 65.6,35.5 R791.2@65.6,34.5
N00400043: Q826.2 Q826.3 | length 0.7
  TOP w0.25: Q826.2@85,47.225 Q826.3@85.65,47.225
N00400047: C775.1 IC744.5 Q743.3 R793.1 | length 21.5
  TOP w0.25: R793.1@65.6,34.5 65.6,33.5 65.85,33.25 69.25,33.25 69.5,33.5 69.5,35.5 69.75,35.75 70.525,35.75 v1(71.15,36.375) IC744.5@71.15,37.4 ; Q743.3@66.75,42.15 67.127,42.15 67.4,41.877 v1(67.4,41)
  BOTTOM w0.25: v1(67.4,41) 67.74,41 68.75,39.99 68.75,36 69,35.75 70.525,35.75 v1(71.15,36.375) 71.35,36.575 C775.1@71.35,37.5
N00400048: C869.1 IC743.5 Q741.3 R790.2 | length 10.5
  TOP w0.25: IC743.5@63.65,37.4 v1(63.65,36.375) 64.275,35.75 67.15,35.75 ; Q741.3@66.75,37.4 67.178,37.4 67.4,37.178 67.4,36 ; R790.2@67.9,34.5 67.9,35.5 67.65,35.75 ; 67.15,35.75 67.65,35.75 ; 67.15,35.75 67.4,36 ; 67.4,36 67.65,35.75
  BOTTOM w0.25: v1(63.65,36.375) 63.85,36.575 C869.1@63.85,37.5
N00400049: C775.2 IC744.4 R792.2 | length 5.9
  TOP w0.25: v1(68.125,36.375) v1(69.85,36.375) IC744.4@69.85,37.4
  BOTTOM w0.25: R792.2@67.9,34.5 67.9,35.525 68.125,35.75 v1(68.125,36.375) ; C775.2@69.65,37.5 69.65,36.575 v1(69.85,36.375)
N00400050: IC745.4 R797.1 | length 6.2
  TOP w0.25: v1(64.875,46.9) IC745.4@65.8,46.9
  BOTTOM w0.25: v1(64.875,46.9) 64.875,51 65.125,51.25 R797.1@65.9,51.25
N00400051: C772.1 C773.1 C890.1 CN407.1 R790.1 R792.1 R799.2 | length 26.6
  TOP w0.5: v1(71.1,33.125) R790.1@71.1,34.5
  BOTTOM w0.5: R792.1@71.1,34.5 v1(71.1,33.125) 75.75,33.125 76.625,32.25 80.35,32.25 80.6,32 C773.1@80.6,31.25 ; C890.1@80.6,22.5 81.48,22.5 81.73,22.75 81.73,27.045 81.275,27.5 C772.1@81.275,28.75 81.275,29.825 80.6,30.5 C773.1@80.6,31.25 ; R799.2@83.5,31.1 82.25,31.1 82.1,31.25 C773.1@80.6,31.25
N00400052: Q742.2 Q742.3 | length 0.7
  TOP w0.25: Q742.2@63,47.225 Q742.3@63.65,47.225
N00400054: C772.2 C773.2 R791.1 R793.2 R798.2 | length 23.3
  TOP w0.5: v1(62.4,33.125) R793.2@62.4,34.5
  BOTTOM w0.5: R791.1@62.4,34.5 v1(62.4,33.125) 69.875,33.125 70.75,32.25 75.5,32.25 76,31.75 R798.2@76,31.1 77.25,31.1 77.4,31.25 C773.2@78.9,31.25 78.9,30.5 78.225,29.825 C772.2@78.225,28.75
N00400056: C890.2 CN407.2 R798.1 R799.1 | length 21.8
  BOTTOM w0.5: R798.1@76,29.4 76,27.27 CN407.2@77.77,25.5 77.77,22.75 78.02,22.5 C890.2@78.9,22.5 78.9,21.75 79.15,21.5 83.25,21.5 83.5,21.75 R799.1@83.5,29.4
N00400057: Q742.6 R782.2 | length 19.1
  TOP w0.25: v1(60.5,49.275) Q742.6@62.35,49.275
  BOTTOM w0.25: v1(60.5,49.275) 60.5,45.75 60.25,45.5 60.25,38.75 60.5,38.5 65.65,38.5 65.9,38.75 R782.2@65.9,39.5
N00400058: Q741.2 R786.1 R788.2 | length 13.7
  TOP w0.25: v1(63.85,43.25) 64.609,43.25 65.093,42.766 65.093,40.607 Q741.2@66.1,39.6
  BOTTOM w0.25: R788.2@62.15,49.25 62.75,49.25 63,49 63,43.5 63.25,43.25 v1(63.85,43.25) R786.1@63.85,42
N00400059: IC741.4 R780.1 R786.2 | length 3.9
  TOP w0.25: IC741.4@62.05,41.9 62.15,42 v1(62.15,43.25)
  BOTTOM w0.25: R786.2@62.15,42 v1(62.15,43.25) R780.1@62.15,44.5
N00400060: C770.2 IC741.3 R782.1 R784.2 | length 16.9
  TOP w0.25: IC741.3@62.05,44.6 v1(62.05,45.75)
  BOTTOM w0.25: C770.2@62.15,47.25 62.15,46.6 62.05,46.5 v1(62.05,45.75) 61.25,44.95 61.25,41.375 61.375,41.25 64.875,41.25 65.75,40.375 67.35,40.375 67.6,40.125 R782.1@67.6,39.5 R784.2@67.6,37.5
N00400062: C770.1 R780.2 | length 2.7
  BOTTOM w0.25: R780.2@63.85,44.5 C770.1@63.85,47.25
N00400063: Q741.1 R784.1 | length 9.2
  TOP w0.25: Q741.1@67.4,39.6 67.888,39.6 68.251,39.963 68.251,40.471 v1(68.768,40.988)
  Mid-Layer 1 w0.25: v1(66.1,36.375) 68.768,39.043 v1(68.768,40.988)
  BOTTOM w0.25: R784.1@65.9,37.5 65.9,36.575 v1(66.1,36.375)
N00400066: C930.2 IC823.3 R962.1 R964.2 | length 16.9
  TOP w0.25: IC823.3@76.55,44.6 v1(76.55,45.75)
  BOTTOM w0.25: C930.2@76.65,47.25 76.65,46.6 76.55,46.5 v1(76.55,45.75) 75.75,44.95 75.75,41.375 75.875,41.25 79.375,41.25 80.25,40.375 81.85,40.375 82.1,40.125 R962.1@82.1,39.5 R964.2@82.1,37.5
N00400067: IC742.4 R781.1 R787.2 | length 6.1
  TOP w0.25: IC742.4@69.55,41.9 v1(69.55,43.25)
  BOTTOM w0.25: v1(69.55,43.25) 69.55,43.8 69.65,43.9 R781.1@69.65,44.5 69.65,45.025 71.35,46.725 R787.2@71.35,47.25
N00400068: C771.2 IC742.3 R783.1 R785.2 | length 6.5
  TOP w0.25: v1(68.625,44.5) 69.45,44.5 IC742.3@69.55,44.6
  BOTTOM w0.25: v1(68.625,44.5) R783.1@67.6,44.5 R785.2@67.6,42 C771.2@69.65,42
N00400069: Q744.2 Q744.3 | length 0.7
  TOP w0.25: Q744.2@70.5,47.225 Q744.3@71.15,47.225
N00400070: Q744.6 R783.2 | length 9.1
  TOP w0.25: Q744.6@69.85,49.275 69.85,48.5 70.1,48.25 v1(70.5,48.25)
  BOTTOM w0.25: R783.2@65.9,44.5 65.9,45.25 66.15,45.5 69.375,45.5 70.5,46.625 v1(70.5,48.25)
N00400072: Q743.2 R787.1 R789.2 | length 9.8
  TOP w0.25: v1(64.875,44.35) Q743.2@66.1,44.35
  BOTTOM w0.25: v1(64.875,44.35) 64.875,45.35 65.65,46.125 ; R789.2@65.9,47.25 65.9,46.375 ; R787.1@69.65,47.25 69.65,46.5 69.275,46.125 66.15,46.125 ; 65.65,46.125 65.9,46.375 ; 65.65,46.125 66.15,46.125 ; 65.9,46.375 66.15,46.125
N00400073: Q743.1 R785.1 | length 3.6
  TOP w0.25: v1(65.9,43.147) 66.99,43.147 67.4,43.557 Q743.1@67.4,44.35
  BOTTOM w0.25: R785.1@65.9,42 v1(65.9,43.147)
N00400074: C771.1 R781.2 | length 2.5
  BOTTOM w0.25: C771.1@71.35,42 R781.2@71.35,44.5
N00400082: C765.2 IC737.4 R872.2 | length 5.9
  TOP w0.25: v1(97.125,36.375) v1(98.85,36.375) IC737.4@98.85,37.4
  BOTTOM w0.25: R872.2@96.9,34.5 96.9,35.525 97.125,35.75 v1(97.125,36.375) ; C765.2@98.65,37.5 98.65,36.575 v1(98.85,36.375)
N00400084: IC738.6 R876.1 | length 2.4
  TOP w0.25: IC738.6@96.7,46.9 v1(96.7,48.25)
  BOTTOM w0.25: R876.1@96.6,49.25 96.6,48.725 96.7,48.625 v1(96.7,48.25)
N00400085: IC738.4 R877.1 | length 6.2
  TOP w0.25: v1(93.875,46.9) IC738.4@94.8,46.9
  BOTTOM w0.25: v1(93.875,46.9) 93.875,51 94.125,51.25 R877.1@94.9,51.25
N00400087: C945.1 IC832.5 Q829.3 R993.1 | length 21.6
  TOP w0.25: R993.1@36.6,34.5 36.6,33.5 36.85,33.25 40.25,33.25 40.5,33.5 40.5,35.5 40.75,35.75 41.525,35.75 v1(42.15,36.375) IC832.5@42.15,37.4 ; Q829.3@37.75,42.15 38.19,42.15 38.4,41.94 v1(38.4,41)
  BOTTOM w0.25: v1(38.4,41) 38.784,41 39.75,40.034 39.75,36 40,35.75 41.525,35.75 v1(42.15,36.375) 42.35,36.575 C945.1@42.35,37.5
N00400088: C764.1 IC736.5 Q736.3 R870.2 | length 10.5
  TOP w0.25: IC736.5@92.65,37.4 v1(92.65,36.375) 93.275,35.75 96.15,35.75 ; Q736.3@95.75,37.4 96.178,37.4 96.4,37.178 96.4,36 ; R870.2@96.9,34.5 96.9,35.5 96.65,35.75 ; 96.15,35.75 96.65,35.75 ; 96.15,35.75 96.4,36 ; 96.4,36 96.65,35.75
  BOTTOM w0.25: v1(92.65,36.375) 92.85,36.575 C764.1@92.85,37.5
N00400091: C760.2 IC739.3 R862.1 R864.2 | length 16.8
  TOP w0.25: v1(90.125,44.6) IC739.3@91.05,44.6
  BOTTOM w0.25: C760.2@91.15,47.25 91.15,46.15 90.125,45.125 v1(90.125,44.6) 90.125,41.5 90.375,41.25 93.875,41.25 94.75,40.375 96.35,40.375 96.6,40.125 R862.1@96.6,39.5 R864.2@96.6,37.5
N00400092: IC739.4 R860.1 R866.2 | length 3.9
  TOP w0.25: IC739.4@91.05,41.9 91.15,42 v1(91.15,43.25)
  BOTTOM w0.25: R866.2@91.15,42 v1(91.15,43.25) R860.1@91.15,44.5
N00400093: Q736.1 R864.1 | length 9.2
  TOP w0.25: Q736.1@96.4,39.6 96.962,39.6 97.216,39.854 97.216,40.48 v1(97.724,40.988)
  Mid-Layer 1 w0.25: v1(95.1,36.375) 97.724,38.999 v1(97.724,40.988)
  BOTTOM w0.25: R864.1@94.9,37.5 94.9,36.575 v1(95.1,36.375)
N00400094: Q736.2 R866.1 R868.2 | length 13.7
  TOP w0.25: v1(92.85,43.25) 93.557,43.25 94.041,42.766 94.041,40.659 Q736.2@95.1,39.6
  BOTTOM w0.25: R868.2@91.15,49.25 91.75,49.25 92,49 92,43.5 92.25,43.25 v1(92.85,43.25) R866.1@92.85,42
N00400095: Q737.2 Q737.3 | length 0.6
  TOP w0.25: Q737.2@92,47.225 Q737.3@92.65,47.225
N00400096: Q739.6 R863.2 | length 9.1
  TOP w0.25: Q739.6@98.85,49.275 98.85,48.5 99.1,48.25 v1(99.5,48.25)
  BOTTOM w0.25: R863.2@94.9,44.5 94.9,45.25 95.15,45.5 98.375,45.5 99.5,46.625 v1(99.5,48.25)
N00400097: Q738.1 R865.1 | length 3.7
  TOP w0.25: v1(94.9,43.147) 96.073,43.147 96.4,43.474 Q738.1@96.4,44.35
  BOTTOM w0.25: R865.1@94.9,42 v1(94.9,43.147)
N00400098: Q738.2 R867.1 R869.2 | length 9.8
  TOP w0.25: v1(93.875,44.35) Q738.2@95.1,44.35
  BOTTOM w0.25: v1(93.875,44.35) 93.875,45.35 94.65,46.125 ; R869.2@94.9,47.25 94.9,46.375 ; R867.1@98.65,47.25 98.65,46.5 98.275,46.125 95.15,46.125 ; 94.65,46.125 94.9,46.375 ; 94.65,46.125 95.15,46.125 ; 94.9,46.375 95.15,46.125
N00400100: C760.1 R860.2 | length 2.7
  BOTTOM w0.25: R860.2@92.85,44.5 C760.1@92.85,47.25
N00400101: Q739.2 Q739.3 | length 0.7
  TOP w0.25: Q739.2@99.5,47.225 Q739.3@100.15,47.225
N00400102: Q737.6 R862.2 | length 19.4
  TOP w0.25: v1(89.5,49.275) Q737.6@91.35,49.275
  BOTTOM w0.25: v1(89.5,49.275) 89.5,46 89,45.5 89,38.75 89.25,38.5 94.65,38.5 94.9,38.75 R862.2@94.9,39.5
N00400104: IC730.4 R861.1 R867.2 | length 6.1
  TOP w0.25: IC730.4@98.55,41.9 v1(98.55,43.25)
  BOTTOM w0.25: v1(98.55,43.25) 98.55,43.8 98.65,43.9 R861.1@98.65,44.5 98.65,45.025 100.35,46.725 R867.2@100.35,47.25
N00400106: C761.2 IC730.3 R863.1 R865.2 | length 6.5
  TOP w0.25: v1(97.625,44.5) 98.45,44.5 IC730.3@98.55,44.6
  BOTTOM w0.25: v1(97.625,44.5) R863.1@96.6,44.5 R865.2@96.6,42 C761.2@98.65,42
N00400107: C765.1 IC737.5 Q738.3 R873.1 | length 21.5
  TOP w0.25: R873.1@94.6,34.5 94.6,33.5 94.85,33.25 98.25,33.25 98.5,33.5 98.5,35.5 98.75,35.75 99.525,35.75 v1(100.15,36.375) IC737.5@100.15,37.4 ; Q738.3@95.75,42.15 96.127,42.15 96.4,41.877 v1(96.4,41)
  BOTTOM w0.25: v1(96.4,41) 96.696,41 97.75,39.946 97.75,36 98,35.75 99.525,35.75 v1(100.15,36.375) 100.35,36.575 C765.1@100.35,37.5
N00400110: Q826.6 R963.2 | length 9.1
  TOP w0.25: Q826.6@84.35,49.275 84.35,48.5 84.6,48.25 v1(85,48.25)
  BOTTOM w0.25: R963.2@80.4,44.5 80.4,45.25 80.65,45.5 83.875,45.5 85,46.625 v1(85,48.25)
N00400111: C764.2 IC736.4 R871.2 | length 6.8
  TOP w0.25: v1(91.35,36.375) IC736.4@91.35,37.4
  BOTTOM w0.25: C764.2@91.15,37.5 91.15,36.575 v1(91.35,36.375) 91.975,35.75 94.35,35.75 94.6,35.5 R871.2@94.6,34.5
N00400114: C761.1 R861.2 | length 2.5
  BOTTOM w0.25: C761.1@100.35,42 R861.2@100.35,44.5
N00400115: C782.2 C783.2 R891.1 R893.2 R898.2 | length 26.7
  TOP w0.5: v1(47.9,33.125) R893.2@47.9,34.5
  BOTTOM w0.5: R891.1@47.9,34.5 v1(47.9,33.125) 48.625,33.125 49.5,32.25 60.25,32.25 61.4,31.1 R898.2@65.25,31.1 66.5,31.1 66.65,31.25 C783.2@68.15,31.25 68.15,30.5 67.475,29.825 C782.2@67.475,28.75
N00400117: CN935.1 IC747.1 R895.1 R914.1 | length 28
  TOP w0.25: CN935.1@55.65,58.98 57.58,58.98 v1(58,59.4) ; IC747.1@56.65,39.6 v1(58.5,39.6) ; v1(56.85,48.25) v1(58.5,48.25)
  BOTTOM w0.25: v1(56.85,48.25) R895.1@56.85,49.25 ; R914.1@57,59.4 v1(58,59.4) 58.5,58.9 v1(58.5,48.25) v1(58.5,39.6)
N00400121: C934.1 IC825.5 Q823.3 R970.2 | length 10.5
  TOP w0.25: IC825.5@78.15,37.4 v1(78.15,36.375) 78.775,35.75 81.65,35.75 ; Q823.3@81.25,37.4 81.678,37.4 81.9,37.178 81.9,36 ; R970.2@82.4,34.5 82.4,35.5 82.15,35.75 ; 81.65,35.75 82.15,35.75 ; 81.65,35.75 81.9,36 ; 81.9,36 82.15,35.75
  BOTTOM w0.25: v1(78.15,36.375) 78.35,36.575 C934.1@78.35,37.5
N00400122: C784.2 IC746.4 R891.2 | length 6.8
  TOP w0.25: v1(47.85,36.375) IC746.4@47.85,37.4
  BOTTOM w0.25: C784.2@47.65,37.5 47.65,36.575 v1(47.85,36.375) 48.475,35.75 50.85,35.75 51.1,35.5 R891.2@51.1,34.5
N00400123: C785.2 IC747.4 R892.2 | length 5.9
  TOP w0.25: v1(53.625,36.375) v1(55.35,36.375) IC747.4@55.35,37.4
  BOTTOM w0.25: R892.2@53.4,34.5 53.4,35.525 53.625,35.75 v1(53.625,36.375) ; C785.2@55.15,37.5 55.15,36.575 v1(55.35,36.375)
N00400125: C784.1 IC746.5 Q746.3 R890.2 | length 10.5
  TOP w0.25: IC746.5@49.15,37.4 v1(49.15,36.375) 49.775,35.75 52.65,35.75 ; Q746.3@52.25,37.4 52.678,37.4 52.9,37.178 52.9,36 ; R890.2@53.4,34.5 53.4,35.5 53.15,35.75 ; 52.65,35.75 53.15,35.75 ; 52.65,35.75 52.9,36 ; 52.9,36 53.15,35.75
  BOTTOM w0.25: v1(49.15,36.375) 49.35,36.575 C784.1@49.35,37.5
N00400126: C785.1 IC747.5 Q748.3 R893.1 | length 21.5
  TOP w0.25: R893.1@51.1,34.5 51.1,33.5 51.35,33.25 54.75,33.25 55,33.5 55,35.5 55.25,35.75 56.025,35.75 v1(56.65,36.375) IC747.5@56.65,37.4 ; Q748.3@52.25,42.15 52.627,42.15 52.9,41.877 v1(52.9,41)
  BOTTOM w0.25: v1(52.9,41) 53.262,41 54.25,40.012 54.25,36 54.5,35.75 56.025,35.75 v1(56.65,36.375) 56.85,36.575 C785.1@56.85,37.5
N00400127: C780.2 IC749.3 R882.1 R884.2 | length 16.8
  TOP w0.25: v1(46.625,44.6) IC749.3@47.55,44.6
  BOTTOM w0.25: C780.2@47.65,47.25 47.65,46.125 46.625,45.1 v1(46.625,44.6) 46.625,41.5 46.875,41.25 50.375,41.25 51.25,40.375 52.85,40.375 53.1,40.125 R882.1@53.1,39.5 R884.2@53.1,37.5
N00400128: Q746.1 R884.1 | length 9.2
  TOP w0.25: Q746.1@52.9,39.6 53.401,39.6 53.773,39.972 53.773,40.471 v1(54.29,40.988)
  Mid-Layer 1 w0.25: v1(51.6,36.375) 54.29,39.065 v1(54.29,40.988)
  BOTTOM w0.25: R884.1@51.4,37.5 51.4,36.575 v1(51.6,36.375)
N00400131: IC749.4 R880.1 R886.2 | length 3.9
  TOP w0.25: IC749.4@47.55,41.9 47.65,42 v1(47.65,43.25)
  BOTTOM w0.25: R886.2@47.65,42 v1(47.65,43.25) R880.1@47.65,44.5
N00400132: IC748.4 R897.1 | length 6.2
  TOP w0.25: v1(50.375,46.9) IC748.4@51.3,46.9
  BOTTOM w0.25: v1(50.375,46.9) 50.375,51 50.625,51.25 R897.1@51.4,51.25
N00400133: IC824.4 R961.1 R967.2 | length 6.1
  TOP w0.25: IC824.4@84.05,41.9 v1(84.05,43.25)
  BOTTOM w0.25: v1(84.05,43.25) 84.05,43.8 84.15,43.9 R961.1@84.15,44.5 84.15,45.025 85.85,46.725 R967.2@85.85,47.25
N00400134: IC748.6 R896.1 | length 2.4
  TOP w0.25: IC748.6@53.2,46.9 v1(53.2,48.25)
  BOTTOM w0.25: R896.1@53.1,49.25 53.1,48.725 53.2,48.625 v1(53.2,48.25)
N00400136: Q747.2 Q747.3 | length 0.7
  TOP w0.25: Q747.2@48.5,47.225 Q747.3@49.15,47.225
N00400137: C780.1 R880.2 | length 2.7
  BOTTOM w0.25: R880.2@49.35,44.5 C780.1@49.35,47.25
